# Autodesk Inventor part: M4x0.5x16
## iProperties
IsCustomPart: 1
Company: 한국ATC센터
Created: 2009-02
Part Number: M4x0.5x16
Material: 강, 연강
Description: 6각머리 태핑 나사
Document SubType Name: Modeling
Standard: KS B 1003
Designer: KYOUNG IL JANG
Standards Organization: KS
Language: ko-KR
Size Designation: M 4 x 16
Categories: <MemberInstance><Categories><Category DisplayName="조임쇠" InternalName="e4da775c-781d-43d5-af7c-5136215cf5a6" Mnemonic="FSTN"><Category DisplayName="볼트" InternalN
Density: 7.86 g/cm^3
Mass: 2.62973 g
Surface Area: 3.81119 cm^2
Volume: 0.334572 cm^3
Vendor: CBT Solutions
Author: KYOUNG IL JANG
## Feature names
1. Fillet2
